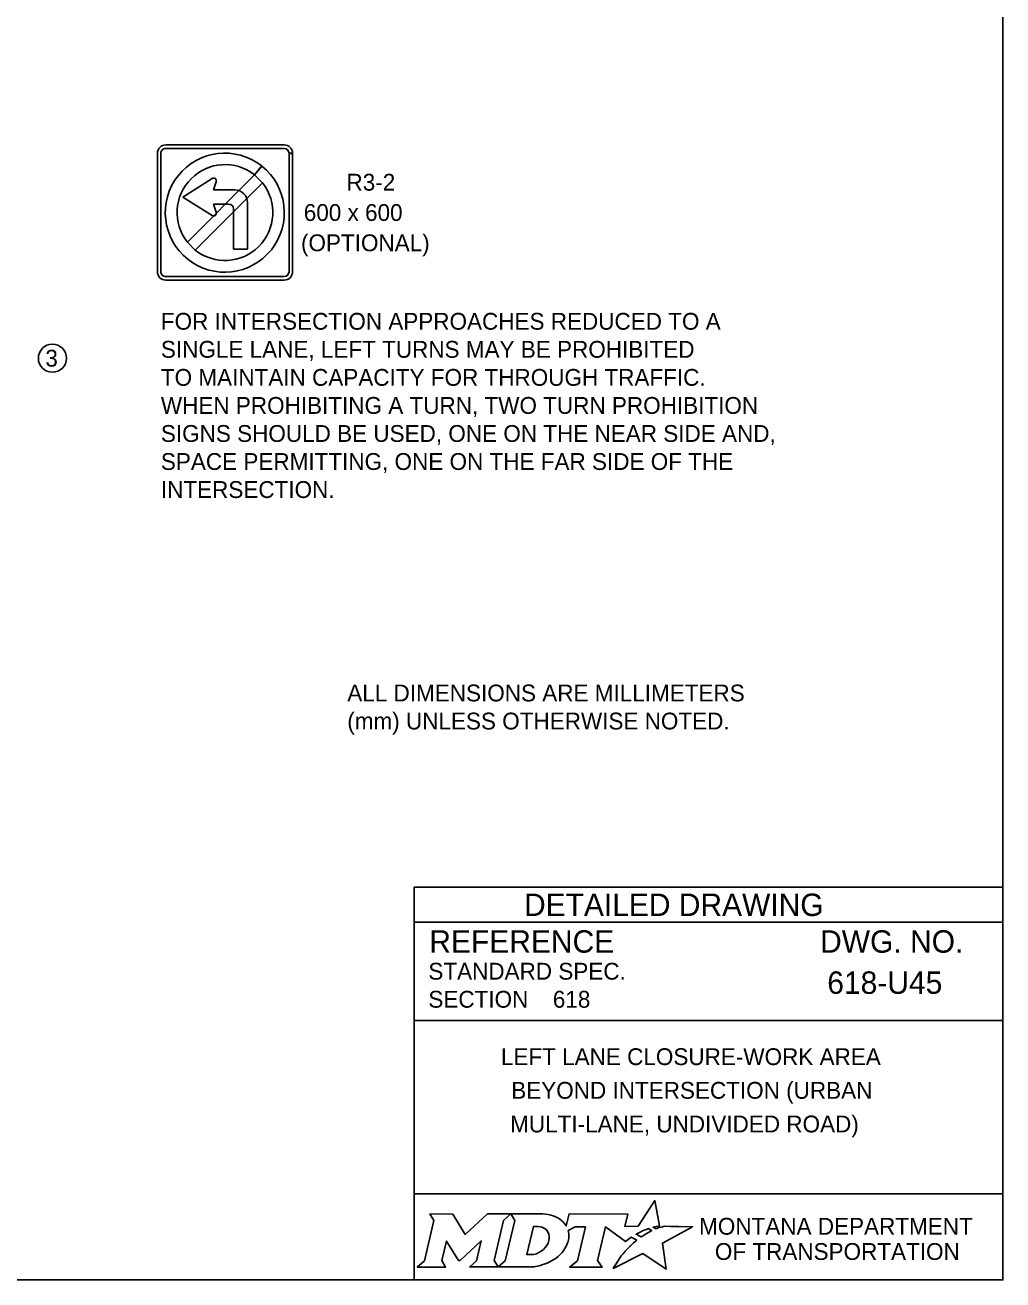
# Model space of a CAD drawing. Extents: x 49991.4 to 50021, y 49987.6 to 50011.4.
# Drawn here: x 50013.262 to 50016.75, y 49987.799 to 49992.273 of the extents above; entities that cross this region are included whole.
import ezdxf

# ---------------------------------------------------------------- set-up
doc = ezdxf.new("R2010")
doc.units = 0
for name, color, linetype in [('Default', 7, 'Continuous'), ('Level 1', 7, 'Continuous'), ('Level 2', 7, 'Continuous'), ('Level 25', 7, 'Continuous'), ('Level 5', 7, 'Continuous')]:
    doc.layers.add(name, color=color, linetype=linetype)

# ---------------------------------------------------------------- blocks, each defined once
blk = doc.blocks.new('R3.1')
at = {"layer": 'Level 25'}
for p, q in [((-35.82, 39.52), (38.27, 39.52)), ((-41.12, 34.23), (-38.91, 34.23)), ((-38.91, 34.23), (-41.12, 34.23)), ((-41.12, -39.86), (-41.12, 34.19)), ((-41.12, 34.19), (-38.91, 34.19)), ((-38.91, 34.19), (-38.91, -39.86)), ((38.27, 37.32), (-35.82, 37.32)), ((41.36, -39.86), (41.36, 34.23)), ((43.56, 34.23), (43.56, -39.86)), ((-21.92, 26.22), (-17.34, 20.74)), ((-17.22, 20.83), (-21.8, 26.31)), ((-17.34, 20.74), (-22.33, 15.75)), ((-17.34, 20.74), (-22.33, 15.75)), ((-22.33, 15.75), (19.79, -26.37)), ((24.78, -21.38), (-17.34, 20.74)), ((8.36, 11.3), (6.72, 16.46)), ((9.31, 18.47), (27.68, 6.89)), ((9.31, 18.47), (9.31, 18.47)), ((-4.9, 11.3), (8.36, 11.3)), ((-12.9, -25.75), (-12.9, 3.3)), ((8.36, 2.48), (-1.08, 2.48)), ((6.72, -2.69), (8.36, 2.48)), ((27.68, 6.89), (9.31, -4.7)), ((-4.08, -0.52), (-4.08, -25.75)), ((19.79, -26.37), (24.78, -21.38)), ((19.79, -26.37), (24.78, -21.38)), ((-4.08, -25.75), (-12.9, -25.75)), ((-35.82, -42.95), (38.27, -42.95)), ((38.27, -45.15), (-35.82, -45.15))]:
    blk.add_line(p, q, dxfattribs=at)
for centre, radius, start, end in [((-35.82, 34.23), 5.29, 90, 180), ((38.27, 34.23), 5.29, 0, 90), ((-35.82, 34.23), 3.09, 90, 180), ((1.33, -2.92), 37.27, 128.57303, 128.34072), ((38.27, 34.23), 3.09, 0, 90), ((1.22, -2.82), 29.99, 321.75713, 127.95466), ((1.22, -2.82), 29.99, 141.7565, 308.24287), ((8.38, 16.99), 1.75, 57.75701, 197.61864), ((1.22, -2.82), 29.99, 44.28688, 44.41635), ((-4.9, 3.3), 8, 90, 180), ((-1.08, -0.52), 3, 90, 180), ((8.38, -3.22), 1.75, 162.38039, 302.24384), ((1.22, -2.82), 29.99, 220.85636, 220.87145), ((-35.82, -39.86), 5.29, 180, 270), ((-35.82, -39.86), 3.09, 180, 270), ((38.27, -39.86), 5.29, 270, 0), ((38.27, -39.86), 3.09, 270, 0)]:
    blk.add_arc(centre, radius, start, end, dxfattribs=at)

msp = doc.modelspace()

# ---------------------------------------------------------------- linework, layer by layer
at = {"layer": 'Default'}
for points in [[(50015.5126, 49987.9811), (50015.5023, 49987.9867), (50015.5139, 49987.9895), (50015.5255, 49987.9915), (50015.5081, 49988.0816), (50015.4486, 49987.9903), (50015.4013, 49987.9896), (50015.4116, 49988.0337), (50015.2024, 49988.0338), (50015.1923, 49987.9913), (50015.1865, 49987.9996)], [(50014.7056, 49988.0338), (50014.7197, 49988.0104), (50014.6862, 49987.8671), (50014.6605, 49987.8446), (50014.7621, 49987.8446), (50014.7486, 49987.8674), (50014.7648, 49987.9375), (50014.8085, 49987.8685), (50014.8138, 49987.8685), (50014.8889, 49987.938), (50014.8725, 49987.8669), (50014.8478, 49987.8449), (50014.9494, 49987.8449), (50014.9356, 49987.8682), (50014.9688, 49988.0106)], [(50014.9688, 49988.0106), (50014.9941, 49988.0338), (50014.9117, 49988.0338), (50014.8321, 49987.9608), (50014.7876, 49988.0335), (50014.7056, 49988.0338)], [(50015.1077, 49988.0338), (50014.9941, 49988.0338), (50015.0088, 49988.0109), (50014.9749, 49987.8671), (50014.9494, 49987.8449), (50015.06, 49987.8449)], [(50015.1317, 49987.9471), (50015.1305, 49987.939), (50015.1273, 49987.9297), (50015.1231, 49987.9215), (50015.1175, 49987.914), (50015.111, 49987.9071), (50015.1031, 49987.9008), (50015.0948, 49987.8961), (50015.0857, 49987.8922), (50015.0766, 49987.8899), (50015.0674, 49987.889), (50015.0515, 49987.889), (50015.0751, 49987.989), (50015.0911, 49987.989), (50015.0987, 49987.9884), (50015.1063, 49987.9865), (50015.1129, 49987.9835), (50015.119, 49987.9793), (50015.1238, 49987.9743), (50015.1275, 49987.9683), (50015.1302, 49987.9621), (50015.1318, 49987.9547), (50015.1318, 49987.9517), (50015.1317, 49987.9471)], [(50015.1991, 49987.9747), (50015.2237, 49987.9878), (50015.2606, 49987.9878), (50015.232, 49987.8673), (50015.2045, 49987.8446), (50015.3207, 49987.8446), (50015.3037, 49987.8675), (50015.3319, 49987.9877), (50015.4032, 49987.936), (50015.4243, 49987.9511), (50015.444, 49987.9402)], [(50015.3882, 49987.8843), (50015.3729, 49987.8599), (50015.3682, 49987.8524), (50015.3624, 49987.8438), (50015.3601, 49987.8395), (50015.4654, 49987.8926), (50015.5493, 49987.8375), (50015.5362, 49987.9302), (50015.6431, 49987.9886), (50015.5938, 49987.9894), (50015.5637, 49987.9898), (50015.5429, 49987.9901), (50015.5361, 49987.9886), (50015.5312, 49987.9874), (50015.5228, 49987.9851), (50015.5126, 49987.9811)], [(50015.4622, 49987.9535), (50015.4598, 49987.9518), (50015.4415, 49987.9614), (50015.4518, 49987.9671), (50015.4559, 49987.9693), (50015.4645, 49987.9733), (50015.4702, 49987.9759), (50015.4781, 49987.9789), (50015.4854, 49987.9816), (50015.4972, 49987.9742), (50015.4932, 49987.9721), (50015.4886, 49987.9696), (50015.4844, 49987.9674), (50015.4794, 49987.9645), (50015.4775, 49987.9634), (50015.4748, 49987.9618), (50015.4723, 49987.9604), (50015.47, 49987.9588), (50015.4674, 49987.957), (50015.4647, 49987.9552), (50015.4622, 49987.9535)], [(50015.4021, 49987.9004), (50015.4021, 49987.9004)], [(50015.1057, 49987.8522), (50015.1141, 49987.8548), (50015.1271, 49987.8602), (50015.1475, 49987.8712)]]:
    msp.add_lwpolyline(points, dxfattribs=at)
for centre, radius, start, end in [((50015.1308, 49987.9554), 0.0709, 339.5329, 15.8582), ((50015.0868, 49987.9727), 0.1183, 300.9103, 339.1383)]:
    msp.add_arc(centre, radius, start, end, dxfattribs=at)
for centre, major_axis, ratio, start_param, end_param in [((50015.1056, 49987.9864), (0.0834, -0.0037), 0.568097, 0.61298, 1.570796), ((50015.1612, 49987.9937), (0.0361, -0.0295), 0.469099, 1.225588, 1.570796), ((50015.4119, 49987.9106), (-0.0098, -0.0102), 0.016458, 3.141593, 6.279097), ((50015.4329, 49987.9305), (-0.0112, -0.0097), 0.021651, 3.157348, 6.283185), ((50015.3952, 49987.8923), (-0.00694, -0.00806), 0.008222, 0, 3.137361), ((50015.0603, 49987.9932), (0, 0.1484), 0.987302, 3.139398, 3.456847)]:
    msp.add_ellipse(centre, major_axis=major_axis, ratio=ratio, start_param=start_param, end_param=end_param, dxfattribs=at)
at = {"layer": 'Level 1'}
for p, q in [((50016.3862, 49988.8587), (50016.3862, 49988.8587)), ((50015.1444, 49988.7993), (50015.1444, 49988.7993)), ((50015.7001, 49988.4747), (50015.7001, 49988.4747))]:
    msp.add_line(p, q, dxfattribs=at)
msp.add_lwpolyline([(49999.3835, 49998.9992), (50016.7501, 49998.9992), (50016.7501, 49987.7988), (49999.3835, 49987.7988)], close=True, dxfattribs=at)
at = {"layer": 'Level 2'}
msp.add_circle((50013.3593, 49991.0851), 0.0501, dxfattribs=at)
at = {"layer": 'Level 5'}
for p, q in [((50016.7501, 49989.1988), (50014.6501, 49989.1988)), ((50014.6501, 49989.1988), (50014.6501, 49987.7988)), ((50016.7501, 49989.0738), (50014.6501, 49989.0738)), ((50016.3862, 49988.8587), (50016.3862, 49988.8587)), ((50015.1444, 49988.7993), (50015.1444, 49988.7993)), ((50016.7501, 49988.7238), (50014.6501, 49988.7238)), ((50015.7001, 49988.4747), (50015.7001, 49988.4747)), ((50016.7501, 49988.1057), (50014.6501, 49988.1057))]:
    msp.add_line(p, q, dxfattribs=at)

# ---------------------------------------------------------------- block references
at = {"layer": 'Level 1', "xscale": 0.005696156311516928, "yscale": -0.0056961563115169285, "rotation": 179.9999999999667}
msp.add_blockref('R3.1', (50013.9818, 49991.6206), dxfattribs=at)

# ---------------------------------------------------------------- texts
at = {"layer": 'Default'}
for s, p in [('MONTANA DEPARTMENT', (50015.6663, 49987.96)), ('OF TRANSPORTATION', (50015.7225, 49987.87))]:
    msp.add_text(s, height=0.06, dxfattribs=at).set_placement(p)
at = {"layer": 'Level 2'}
for s, height, p in [('R3-2', 0.06, (50014.4084, 49991.6825)), ('600 x 600', 0.06, (50014.256, 49991.5745)), ('(OPTIONAL)', 0.06, (50014.246, 49991.4665)), ('FOR INTERSECTION APPROACHES REDUCED TO A ', 0.06, (50013.7462, 49991.1867)), ('SINGLE LANE, LEFT TURNS MAY BE PROHIBITED ', 0.06, (50013.7462, 49991.0867)), ('3', 0.06, (50013.3341, 49991.0551)), ('TO MAINTAIN CAPACITY FOR THROUGH TRAFFIC.', 0.06, (50013.7462, 49990.9867)), ('WHEN PROHIBITING A TURN, TWO TURN PROHIBITION ', 0.06, (50013.7462, 49990.8867)), ('SIGNS SHOULD BE USED, ONE ON THE NEAR SIDE AND,', 0.06, (50013.7462, 49990.7867)), ('SPACE PERMITTING, ONE ON THE FAR SIDE OF THE', 0.06, (50013.7462, 49990.6867)), ('INTERSECTION.', 0.06, (50013.7462, 49990.5867)), ('ALL DIMENSIONS ARE MILLIMETERS', 0.06, (50014.4112, 49989.8614)), ('(mm) UNLESS OTHERWISE NOTED.', 0.06, (50014.4112, 49989.7614)), ('618-U45', 0.08, (50016.1235, 49988.8187)), ('618', 0.06, (50015.1444, 49988.7693)), ('618', 0.06, (50015.1445, 49988.7693)), (' LEFT LANE CLOSURE-WORK AREA', 0.06, (50014.9369, 49988.5647)), (' BEYOND INTERSECTION (URBAN ', 0.06, (50014.9738, 49988.4447)), ('MULTI-LANE, UNDIVIDED ROAD)', 0.06, (50014.9922, 49988.3247))]:
    msp.add_text(s, height=height, dxfattribs=at).set_placement(p)
at = {"layer": 'Level 5'}
for s, height, p in [('DETAILED DRAWING', 0.0799, (50015.0418, 49989.0963)), ('REFERENCE', 0.08, (50014.7037, 49988.9654)), ('DWG. NO.', 0.08, (50016.0979, 49988.9654)), ('STANDARD SPEC.', 0.06, (50014.7004, 49988.8694)), ('SECTION', 0.06, (50014.7004, 49988.7694))]:
    msp.add_text(s, height=height, dxfattribs=at).set_placement(p)

doc.saveas('drawing.dxf')
